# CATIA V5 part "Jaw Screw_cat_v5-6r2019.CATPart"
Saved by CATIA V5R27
Part number: Jaw Screw
Bounding box of the stored display mesh (mm): x -9 to 9, y 0 to 138, z -8.994 to 9
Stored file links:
  E:\_Deepak\2017_Deepak\CATIA\Resources\Tutorial Files\Tutorials\c16_catia_v5_6r2016_tut\Bench vice\Jaw Screw_cat_v5-6r2016.CATPart
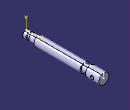
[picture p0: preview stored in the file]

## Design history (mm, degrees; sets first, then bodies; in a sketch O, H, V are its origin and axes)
Body1 (main body)
  Sketch1 on yz-plane, origin (0, 0, 0), H (0, 1, 0), V (0, 0, 1)
    line L1 (0, 0) -> (0, 6)
    line L2 (0, 6) -> (6, 6)
    line L3 (6, 6) -> (6, 4)
    line L4 (6, 4) -> (11, 4)
    line L5 (11, 4) -> (11, 6)
    point P5 (11, 6)
    line L6 (11, 6) -> (22, 6)
    line L7 (22, 6) -> (22, 8)
    line L8 (22, 8) -> (104, 8)
    line L9 (104, 8) -> (104, 6)
    point P9 (104, 6)
    line L10 (104, 6) -> (114, 6)
    line L11 (114, 6) -> (114, 9)
    line L12 (114, 9) -> (138, 9)
    line L13 (138, 9) -> (138, 0)
    point P13 (138, 0)
    line L14 (138, 0) -> (0, 0)
    distance L2 L14 = 6
    distance L8 L14 = 8
    distance L12 L14 = 9
    length L2 = 6
    length L4 = 5
    length L8 = 82
    length L10 = 10
    length L12 = 24
    length L14 = 138
    distance L4 L14 = 4
    vertical: L1 V, L3 V, L5 V, L7 V, L9 V, L11 V, L13 V
    horizontal: L2 H, L4 H, L6 H, L8 H, L10 H, L12 H, L14 H
    coincidence: P5 L2, P9 L6, P13 H
  Shaft1: profile Sketch1, axis edge of Sketch1, angle 360
  Sketch2 on yz-plane, origin (0, 0, 0), H (0, 1, 0), V (0, 0, 1)
    circle A1 centre (126, 0) radius 3
    point P1 (126, 0)
    radius A1 = 3
    distance P1 V = 126
    coincidence: P1 H
  Pocket1: profile Sketch2, direction (-1, 0, 0), length 20, mirrored extent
